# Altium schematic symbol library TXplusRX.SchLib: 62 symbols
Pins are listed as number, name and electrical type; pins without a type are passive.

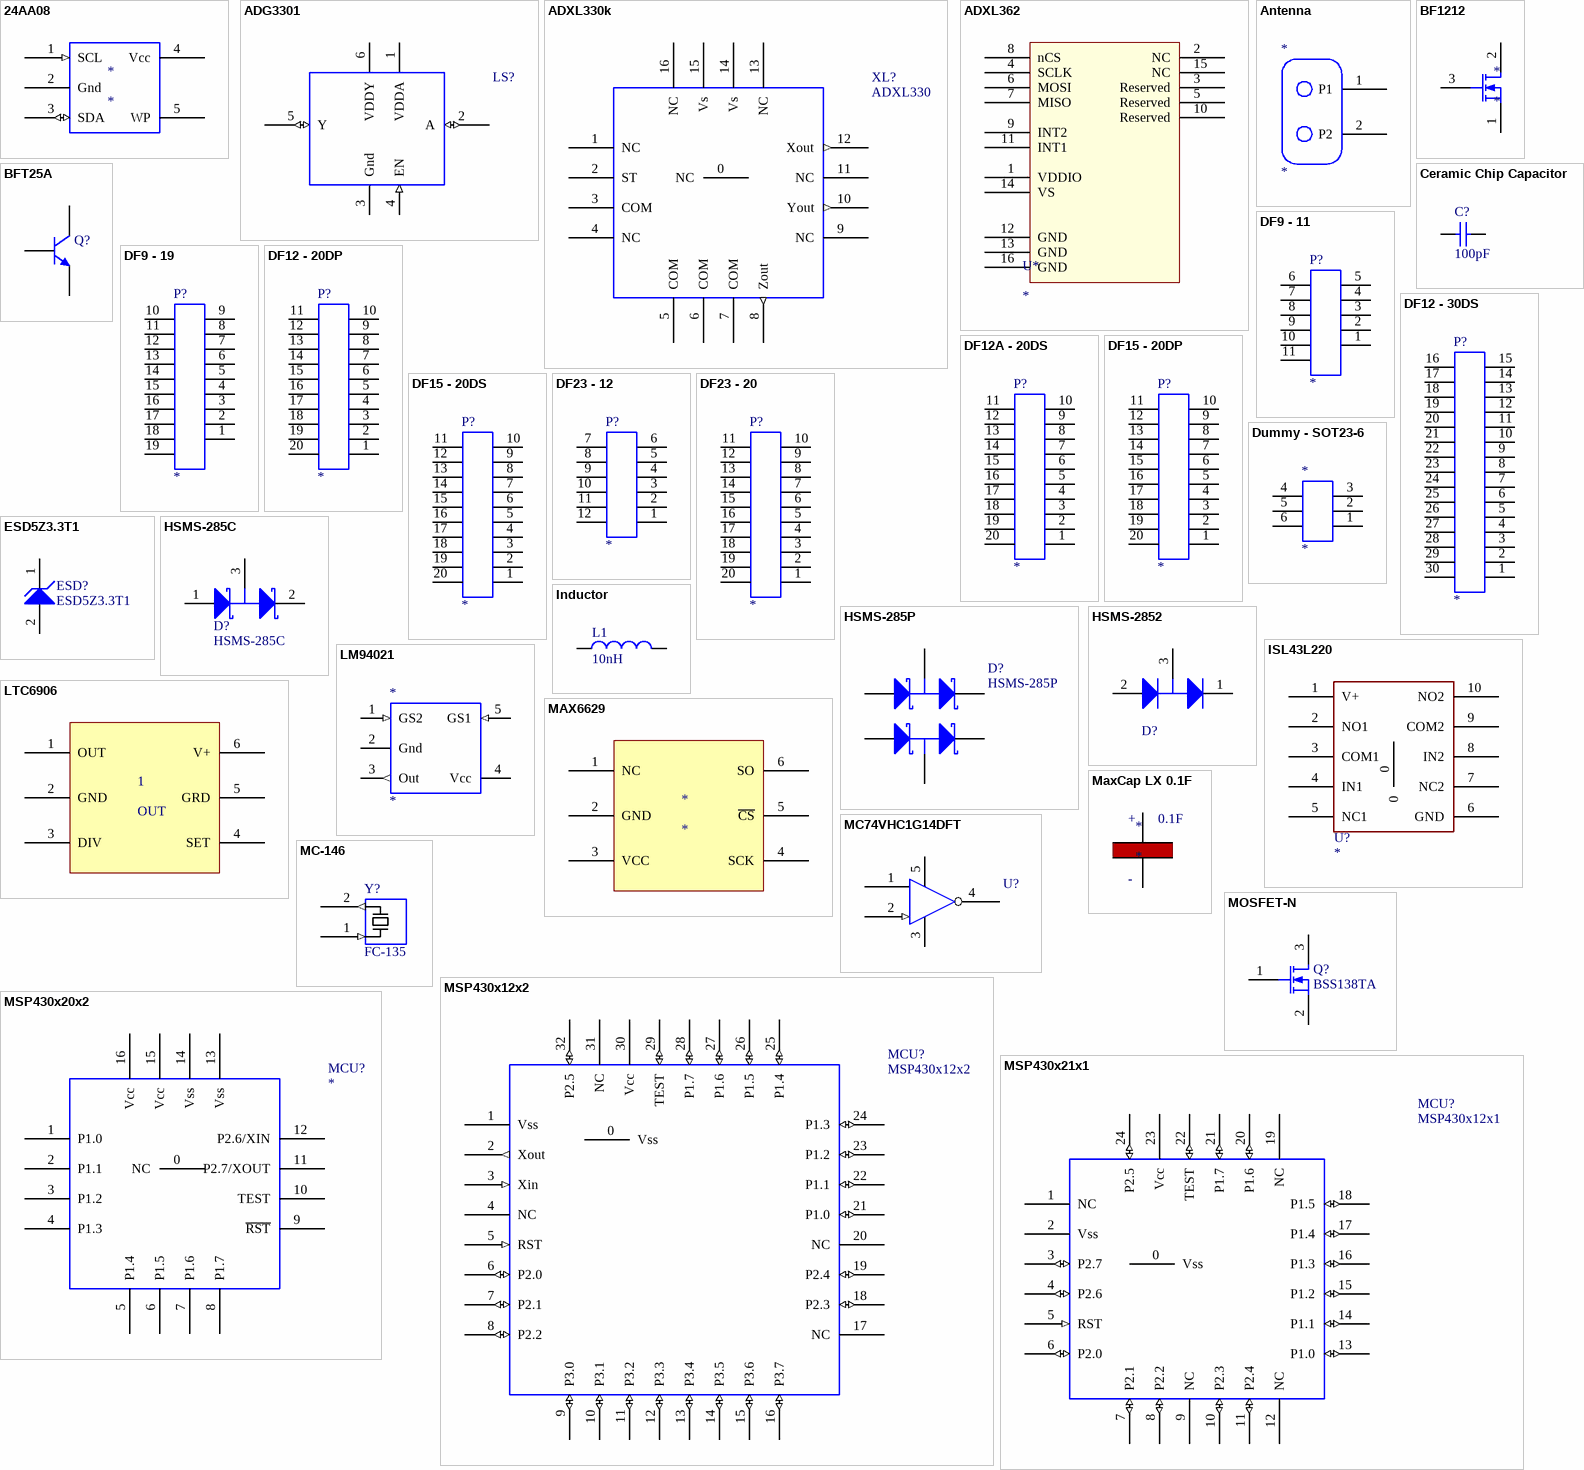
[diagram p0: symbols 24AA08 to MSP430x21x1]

## 24AA08
designator *
Microchip Technology - I2C SERIAL 8K EEPROM - 1.7v
footprint SOT-23-5 (SOT23, 5-Leads, Body 3.0x3.0mm (max), Pitch 0.95mm, IPC Medium Density)
pins: 1 SCL (in) "Serial Clock", 2 Gnd, 3 SDA (io) "Serial Address/Data I/O", 4 Vcc, 5 WP "Write_Protect Input"

## ADG3301
designator LS?  (value not drawn)
Level Shifter  Ensure:  VccA < VccY; DNS: Do Not Stuff Part
footprint sc70-6 (DIP; 24 Leads; Row Spacing 15.24 mm; Pitch 2.54 mm)
pins: 1 VDDA (power), 2 A (io) "Low Voltage IO", 3 Gnd (power), 4 EN (in) "Enable Output Translation", 5 Y (io) "High Voltage IO", 6 VDDY (power)

## ADXL330k
designator XL?, comment ADXL330
Analog Devices 3D Accelerometer
footprint 32-QFN - Gnd Pad Only (32-QFN, Gnd Pad Only, for MSP430F1232)
pins: 0 NC, 1 NC, 2 ST "Self Test", 3 COM (power) "GND", 4 NC, 5 COM (power) "GND", 6 COM (power) "GND", 7 COM (power) "GND", 8 Zout (out) "Output", 9 NC, 10 Yout (out), 11 NC, 12 Xout (out) "Output", 13 NC, 14 Vs (power) "2V to 3.6V", 15 Vs (power) "2V to 3.6V", 16 NC

## ADXL362
designator U*
Analog Devices low power accelerometer
footprint ADXL362
pins: 1 VDDIO, 2 NC, 3 Reserved, 4 SCLK, 5 Reserved, 6 MOSI, 7 MISO, 8 nCS, 9 INT2, 10 Reserved, 11 INT1, 12 GND, 13 GND, 14 VS, 15 NC, 16 GND

## Antenna
designator *
footprint antenna
pins: 1 P1 "Output", 2 P2 "Output"

## BF1212
designator *
footprint sot343r (SOT343R Package for BF1212)
pins: 1 S, 2 D, 3 G

## BFT25A
designator Q?
NPN 5 GHz Wideband Transistor; Part Number: BFT25A; DNS: Do Not Stuff Part
footprint SOT-23 (SOT-23; 3 Leads; Body 3.0 x 2.5 mm, inc. leads (LxW max))
pins: 1 B, 2 E, 3 C

## Ceramic Chip Capacitor
designator C?  value 100pF
Ceramic Capacitor - Standard; DNS: Do Not Stuff Part
footprint 0402 (Chip Capacitor; Body 1.0 x 0.5 mm (LxW typ))
footprint 0603 (Chip Capacitor; Body 1.6 x 0.8 mm (LxW typ))
footprint 0805 (Chip Capacitor; Body 2.0 x 1.2 mm (LxW typ))
footprint 1206 (Chip Capacitor; Body 3.2 x 1.6 mm (LxW typ))
footprint 1210 (Chip Capacitor; Body 3.2 x 2.5 mm (LxW typ))
footprint 1812 (Chip Capacitor; Body 4.5 x 3.2 mm (LxW typ))
footprint 1825 (Chip Capacitor; Body 4.5 x 6.4 mm (LxW typ))
pins: 1, 2

## DF9 - 11
designator P?
DF9 - 11 Connector; DNS: Do Not Stuff
footprint DF9 -11 Connector (DF9 -11, 11Pin Connector)
pins: 1, 2, 3, 4, 5, 6, 7, 8, 9, 10, 11

## DF9 - 19
designator P?
DF9 - 19 Connector; DNS: Do Not Stuff
footprint DF9 -19 Connector (DF9 -19, 19 Pin Connector)
pins: 1, 2, 3, 4, 5, 6, 7, 8, 9, 10, 11, 12, 13, 14, 15, 16, 17, 18, 19

## DF12 - 20DP
designator P?
DF12 - 20DP, Connector Header; DNS: Do Not Stuff
footprint DF12 - 20DP (DF12 - 20DP, Connector Header)
pins: 1, 2, 3, 4, 5, 6, 7, 8, 9, 10, 11, 12, 13, 14, 15, 16, 17, 18, 19, 20

## DF12 - 30DS
designator P?
DF12 - 30DS, Connector Receptacle; DNS: Do Not Stuff
footprint DF12 - 30DS (DF12 - 30DS, Connector Receptacle)
pins: 1, 2, 3, 4, 5, 6, 7, 8, 9, 10, 11, 12, 13, 14, 15, 16, 17, 18, 19, 20, 21, 22, 23, 24, 25, 26, 27, 28, 29, 30

## DF12A - 20DS
designator P?
DF12A - 20DS, Connector Receptacle; DNS: Do Not Stuff
footprint DF12 - 20DS (DF12 - 20DS, Connector Receptacle)
pins: 1, 2, 3, 4, 5, 6, 7, 8, 9, 10, 11, 12, 13, 14, 15, 16, 17, 18, 19, 20

## DF15 - 20DP
designator P?
DF15 - 20DP, Connector Header; DNS: Do Not Stuff
footprint DF15 - 20DP (DF15 - 20DP, Connector Header)
pins: 1, 2, 3, 4, 5, 6, 7, 8, 9, 10, 11, 12, 13, 14, 15, 16, 17, 18, 19, 20

## DF15 - 20DS
designator P?
DF15 - 20DS, Connector Receptacle; DNS: Do Not Stuff
footprint DF15 - 20DS (DF15 - 20DS, Connector Receptacle)
pins: 1, 2, 3, 4, 5, 6, 7, 8, 9, 10, 11, 12, 13, 14, 15, 16, 17, 18, 19, 20

## DF23 - 12
designator P?
DF23 - 12, Connector; DNS: Do Not Stuff
footprint DF23 - 12 (DF23 - 12, Connector)
pins: 1, 2, 3, 4, 5, 6, 7, 8, 9, 10, 11, 12

## DF23 - 20
designator P?
DF23 - 20 Connector; DNS: Do Not Stuff
footprint DF23 - 20 (DF23 - 20, Connector)
pins: 1, 2, 3, 4, 5, 6, 7, 8, 9, 10, 11, 12, 13, 14, 15, 16, 17, 18, 19, 20

## Dummy - SOT23-6
designator *
Dummy - SOT23-6
footprint SOT23-6 (SOT-457/SC-74; 6 Leads; Body 3 x 3 mm, inc. leads (LxW max))
pins: 1, 2, 3, 4, 5, 6

## ESD5Z3.3T1
designator ESD?
5V Overvoltage Protection Zener
footprint SOD-523 (SOD-523 Footprint)
pins: 1 C, 2 A

## HSMS-285C
designator D?
Agilent Schottky Diode, Bridge Quad, HSMS-285C
footprint SOT-323, HSMS-285C (SOT-323/SC-70; 3 Leads; HSMS-285C)
pins: 1 A, 2 K, 3 C

## HSMS-285P
designator D?
Agilent Schottky Diode, Bridge Quad, HSMS-285P
footprint SOT-363 (SOT-363 ,SC-88 ,6 Lead)
pins: 1 A, 2 C, 3 K, 4 K, 5 C, 6 A

## HSMS-2852
designator D?  (value not drawn)
Dual Schottky Diode RF
footprint SOT-23  WIDE
pins: 1, 2, 3

## Inductor
designator L1  value 10nH  (hidden comment: Inductor)
footprint 0805 (Chip Capacitor; Body 2.0 x 1.2 mm (LxW typ))
footprint 0603 (Chip Capacitor; Body 1.6 x 0.8 mm (LxW typ))
footprint 1206 (Chip Capacitor; Body 3.2 x 1.6 mm (LxW typ))
footprint 0402 (Chip Capacitor; Body 1.0 x 0.5 mm (LxW typ))
pins: 1, 2

## ISL43L220
designator U?
Ultra Low ON-Resistance, Low Voltage, Single Supply, Dual SPDT Analog Switch
footprint Thin Dual Flat No-Lead plastic Package (TDFN, 10-Leads, Body 3.0x3.0mm (max), Pitch 0.50mm, IPC Medium Density)
pins: 0, 1 V+, 2 NO1, 3 COM1, 4 IN1, 5 NC1, 6 GND, 7 NC2, 8 IN2, 9 COM2, 10 NO2

## LM94021
designator *
Temperature Sensor
footprint SC70 (Ultra low Power LDO - TI)
pins: 1 GS2 (in) "Gain Select 2", 2 Gnd (power), 3 Out (out) "Enable Output Translation", 4 Vcc (power) "Low Voltage IO", 5 GS1 (in) "Gain Select 1"

## LTC6906
designator 1, comment OUT
footprint LTC6906 (SOT23, 6-Leads, Body 2.90x2.80mm, Pitch 0.95mm, IPC Medium Density)
pins: 1 OUT, 2 GND, 3 DIV, 4 SET, 5 GRD, 6 V+

## MAX6629
designator *
footprint MAX6629-6632 (SOT23, 6-Leads, Body 2.90x2.80mm, Pitch 0.95mm, IPC Medium Density)
pins: 1 NC, 2 GND, 3 VCC, 4 SCK, 5 ~{CS}, 6 SO

## MaxCap LX 0.1F
designator *
MaxCap LX 0.1F, low leakage supper cap 5.5v
footprint Maxcap LX 0.1F (Maxcap LX Series, 0.1F, Diameter  11mm, Leads 5.1mm)
pins: 1 Positive (power), 2 GND (power)

## MC74VHC1G14DFT
designator U?  (value not drawn)
1uA CMOS Schmitt-Trigger Inverter
footprint SC70-5
pins: 1 NC, 2 A (in) "Input", 3 Gnd (power), 4 Y "Output", 5 VDD (power)

## MC-146
designator Y?, comment FC-135
FC-135 Crystal D-K SE2416CT (MC-146)
footprint FC-135 (FC-135   crystal - epson eletronics)
pins: 1 (in) "Output", 2 (out) "Output"

## MOSFET-N
designator Q?, comment BSS138TA
N-Channel MOSFET; PackageDocument: 1995/1996
footprint SOT-23 (SOT-23; 3 Leads; Body 3.0 x 2.5 mm, inc. leads (LxW max))
pins: 1 G, 2 S, 3 D

## MSP430x12x2
designator MCU?
32QFN MSP430x12x2
footprint 32-QFN (32-QFN, for MSP430F1232)
pins: 0 Vss (power) "Output", 1 Vss (power) "Output", 2 Xout (out) "Output", 3 Xin (in) "Output", 4 NC "Output", 5 RST (in) "Output", 6 P2.0 (io) "Output", 7 P2.1 (io) "Output", 8 P2.2 (io) "Output", 9 P3.0 (io) "Output", 10 P3.1 (io) "Output", 11 P3.2 (io) "Output", 12 P3.3 (io) "Output", 13 P3.4 (io) "Output", 14 P3.5 (io) "Output", 15 P3.6 (io) "Output", 16 P3.7 (io) "Output", 17 NC "Output", 18 P2.3 (io) "Output", 19 P2.4 (io) "Output", 20 NC "Output", 21 P1.0 (io) "Output", 22 P1.1 (io) "Output", 23 P1.2 (io) "Output", 24 P1.3 (io) "Output", 25 P1.4 (io) "Output", 26 P1.5 (io) "Output", 27 P1.6 (io) "Output", 28 P1.7 (io) "Output", 29 TEST (io) "Output", 30 Vcc (power) "Output", 31 NC "Output", 32 P2.5 (io) "Output"

## MSP430x20x2
designator MCU?
16QFN MSP430x20x2
footprint 16-QFN (16-QFN, LFCSP (CP-16-5) for ADXL330k)
pins: 0 NC, 1 P1.0, 2 P1.1 "Self Test", 3 P1.2 "GND", 4 P1.3, 5 P1.4 "GND", 6 P1.5 "GND", 7 P1.6 "GND", 8 P1.7 "Output", 9 ~{RST}, 10 TEST, 11 P2.7/XOUT, 12 P2.6/XIN "Output", 13 Vss (power), 14 Vss (power) "2V to 3.6V", 15 Vcc (power) "2V to 3.6V", 16 Vcc (power)

## MSP430x21x1
designator MCU?, comment MSP430x12x1
24QFN MSP430x21x1
footprint 24-QFN (24-QFN, for MSP430Fx21x1)
pins: 0 Vss (power) "Output", 1 NC "Output", 2 Vss (power) "Output", 3 P2.7 (io) "Output", 4 P2.6 (io) "Output", 5 RST (in) "Output", 6 P2.0 (io) "Output", 7 P2.1 (io) "Output", 8 P2.2 (io) "Output", 9 NC "Output", 10 P2.3 (io) "Output", 11 P2.4 (io) "Output", 12 NC "Output", 13 P1.0 (io) "Output", 14 P1.1 (io) "Output", 15 P1.2 (io) "Output", 16 P1.3 (io) "Output", 17 P1.4 (io) "Output", 18 P1.5 (io) "Output", 19 NC "Output", 20 P1.6 (io) "Output", 21 P1.7 (io) "Output", 22 TEST (io) "Output", 23 Vcc (power) "Output", 24 P2.5 (io) "Output"

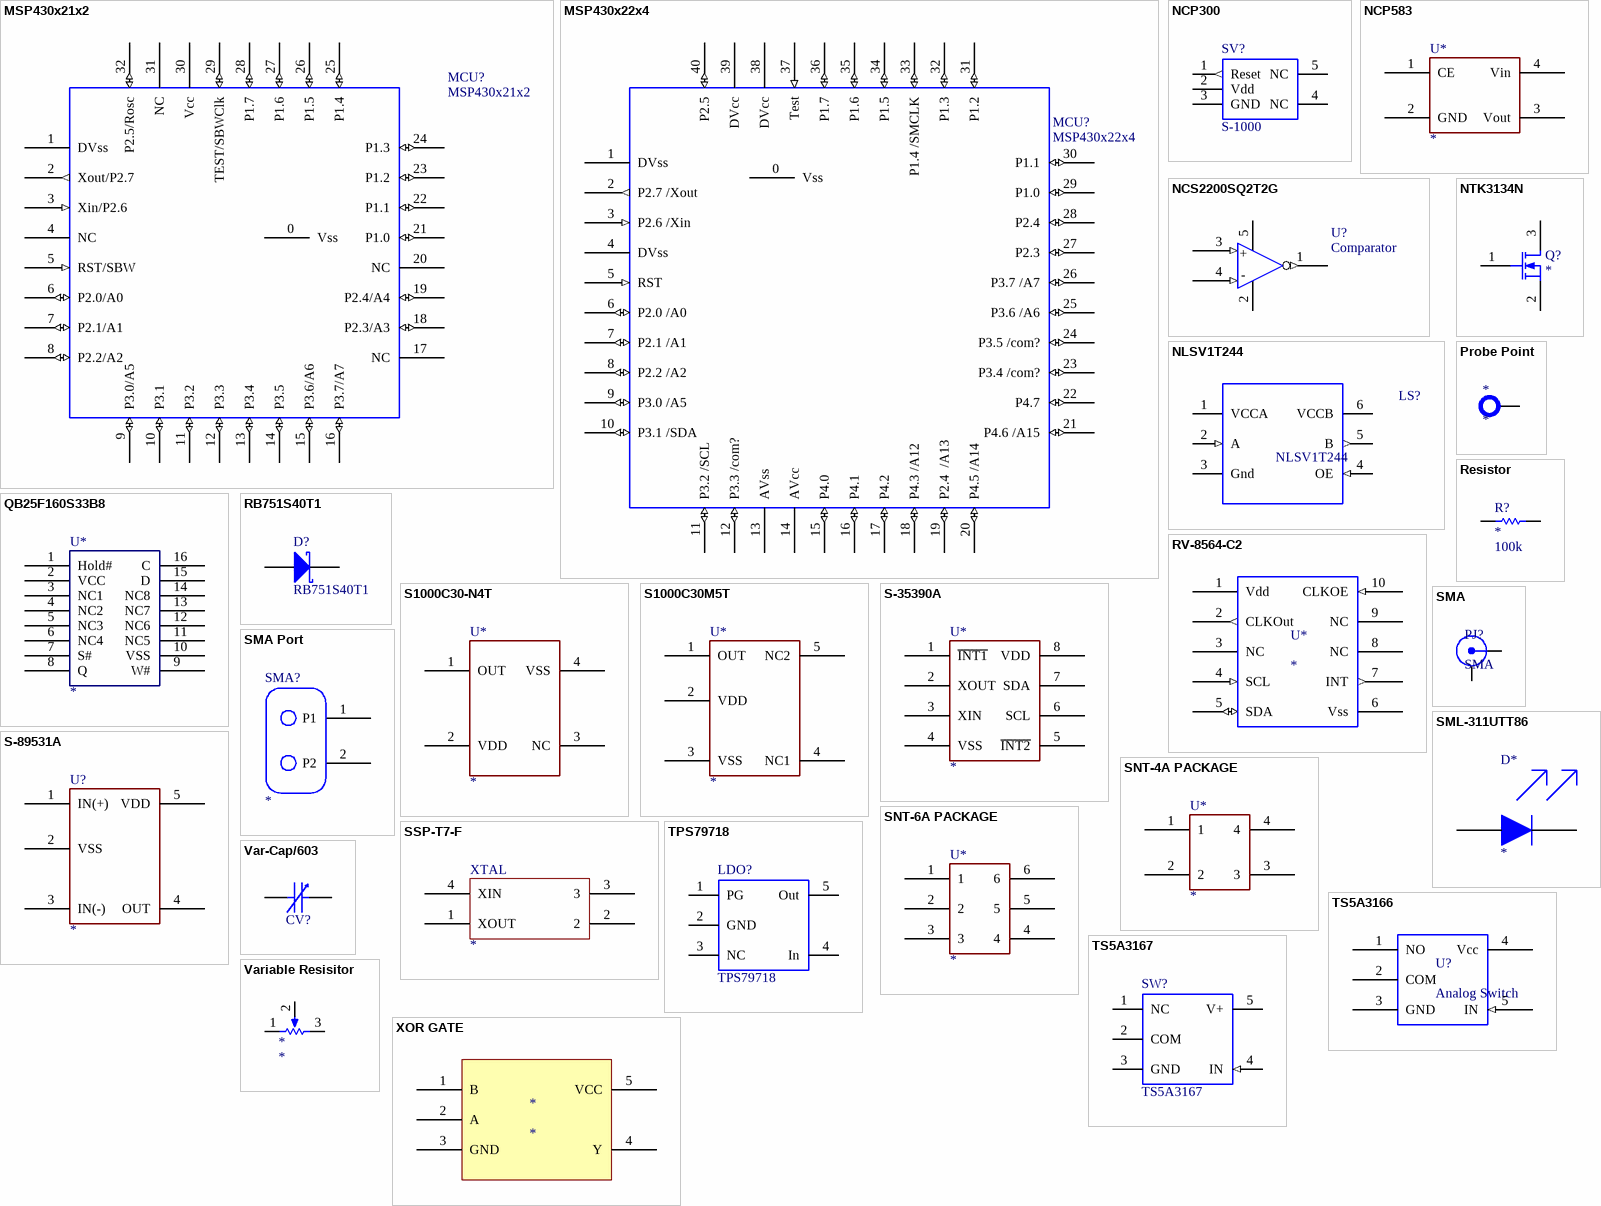
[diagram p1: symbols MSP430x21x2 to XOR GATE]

## MSP430x21x2
designator MCU?
32QFN MSP430x21x2
footprint 32-QFN (32-QFN, for MSP430F1232)
pins: 0 Vss (power) "Output", 1 DVss (power), 2 Xout/P2.7 (out), 3 Xin/P2.6 (in), 4 NC "Output", 5 RST/SBW (in), 6 P2.0/A0 (io), 7 P2.1/A1 (io) "Output", 8 P2.2/A2 (io) "Output", 9 P3.0/A5 (io), 10 P3.1 (io) "Output", 11 P3.2 (io) "Output", 12 P3.3 (io) "Output", 13 P3.4 (io) "Output", 14 P3.5 (io) "Output", 15 P3.6/A6 (io), 16 P3.7/A7 (io), 17 NC "Output", 18 P2.3/A3 (io) "Output", 19 P2.4/A4 (io) "Output", 20 NC "Output", 21 P1.0 (io) "Output", 22 P1.1 (io) "Output", 23 P1.2 (io) "Output", 24 P1.3 (io) "Output", 25 P1.4 (io) "Output", 26 P1.5 (io) "Output", 27 P1.6 (io) "Output", 28 P1.7 (io) "Output", 29 TEST/SBWClk (io) "Output", 30 Vcc (power) "Output", 31 NC "Output", 32 P2.5/Rosc (io) "Output"

## MSP430x22x4
designator MCU?
40QFN MSP430x22x4
footprint 40-QFN (QFN, 40-Leads, Body 6.2x6.2mm (max), Pitch 0.50mm, IPC Medium Density - MSP430x22x4)
pins: 0 Vss (power) "Output", 1 DVss (power) "Output", 2 P2.7 /Xout (out) "Output", 3 P2.6 /Xin (in) "Output", 4 DVss (power) "Output", 5 RST (in), 6 P2.0 /A0 (io), 7 P2.1 /A1 (io), 8 P2.2 /A2 (io), 9 P3.0 /A5 (io), 10 P3.1 /SDA (io), 11 P3.2 /SCL (io), 12 P3.3 /com? (io), 13 AVss (power), 14 AVcc (power), 15 P4.0 (io), 16 P4.1 (io), 17 P4.2 (io), 18 P4.3 /A12 (io), 19 P2.4  /A13 (io), 20 P4.5 /A14 (io), 21 P4.6 /A15 (io), 22 P4.7 (io), 23 P3.4 /com? (io), 24 P3.5 /com? (io), 25 P3.6 /A6 (io), 26 P3.7 /A7 (io), 27 P2.3 (io), 28 P2.4 (io), 29 P1.0 (io), 30 P1.1 (io), 31 P1.2 (io), 32 P1.3 (io), 33 P1.4 /SMCLK (io), 34 P1.5 (io), 35 P1.6 (io), 36 P1.7 (io), 37 Test (in), 38 DVcc (power), 39 DVcc (power), 40 P2.5 (io)

## NCP300
designator SV?, comment S-1000
300nA, 1.8V Supervisor (S-1000 or NCP300LSN)
footprint SOT-23-5 (SOT-23/SC-74A; 5 Leads; Body 3 x 3.1 mm, inc. leads (LxW max))
pins: 1 Reset (out), 2 Vdd (power), 3 GND (power), 4 NC, 5 NC

## NCP583
designator U*
Ultra-Low Iq 150mA CMOS LDO Regulator with Enable
footprint SC82-AB
pins: 1 CE, 2 GND, 3 Vout, 4 Vin

## NCS2200SQ2T2G
designator U?, comment Comparator
On Semi 10uA Comparator
footprint sc70-5 (SC70-5)
pins: 1 OUT (out) "Output", 2 Gnd (power), 3 IN+ (in) "Positive Input", 4 In- (in) "Inverting Input", 5 VDD (power)

## NLSV1T244
designator LS?
Level Shifter: 1-Bit Dual-Supply Non-Inverting Level Translator; Part Number: ADG3301; DNS: Do Not Stuff Part
footprint UDFN6 (UDFN6 - Level Shifter -  NLSV1T244)
pins: 1 VCCA (power) "VDDA", 2 A (in) "Low Voltage IO", 3 Gnd (power), 4 OE (in) "Enable Output Translation", 5 B (out) "High Voltage IO", 6 VCCB (power) "VDDY"

## NTK3134N
designator Q?
Powe Mosfet 20V, 890mA, Single N-channel
footprint SOT723 (SOT723, 3-Leads, Body 1.3x1.3mm (max), Pitch 0.40mm, IPC Medium Density)
pins: 1 G, 2 S, 3 D

## Probe Point
designator *
Probe Point for debug
footprint Probe Point (35mil Pad, 20mil hole size)
pins: 0

## QB25F160S33B8
designator U*
Intel Serial flash memory, 16Mbit, SOIC-16
footprint SOIC16 (SOIC 16)
pins: 1 Hold#, 2 VCC, 3 NC1, 4 NC2, 5 NC3, 6 NC4, 7 S#, 8 Q, 9 W#, 10 VSS, 11 NC5, 12 NC6, 13 NC7, 14 NC8, 15 D, 16 C

## RB751S40T1
designator D?
Schottky Diode
footprint SOD-523 (SOD-523 Footprint)
pins: 1 C, 2 A

## Resistor
designator R?  Vaule: 100k
Thick Film Resistor
footprint 0805 (Chip Capacitor; Body 2.0 x 1.2 mm (LxW typ))
footprint 0402 (Chip Capacitor; Body 1.0 x 0.5 mm (LxW typ))
footprint 0603 (Chip Capacitor; Body 1.6 x 0.8 mm (LxW typ))
pins: 1, 2

## RV-8564-C2
designator U*
RV-8564-C2, Real Time Clock
footprint RV-8564-C2 (RV-8564-C2 RTC Package: LCC, 10-Pins, Body 5.2x3.4mm (max), Pitch 1.00mm, IPC Medium Density)
pins: 1 Vdd (power), 2 CLKOut (out), 3 NC, 4 SCL (in), 5 SDA (io), 6 Vss (power), 7 INT (out), 8 NC, 9 NC, 10 CLKOE (in)

## S1000C30-N4T
designator U*
Ultra-small package High precision protection(SC82-AB)
footprint SC82-AB
pins: 1 OUT, 2 VDD, 3 NC, 4 VSS

## S1000C30M5T
designator U*
Ultra small package High precision voltage protection(SOT-23-5)
footprint SOT-23-5 (SOT-23/SC-74A; 5 Leads; Body 3 x 3.1 mm, inc. leads (LxW max))
pins: 1 OUT, 2 VDD, 3 VSS, 4 NC1, 5 NC2

## S-35390A
designator U*
2-WIRE-REAL-TIME CLOCK(SNT-8A)
footprint SNT-8A
pins: 1 ~{INT1}, 2 XOUT, 3 XIN, 4 VSS, 5 ~{INT2}, 6 SCL, 7 SDA, 8 VDD

## S-89531A
designator U?
0.7uA rail to rail cmos comparator
footprint SC-88A (SC-88A 5-Leads, Body 2.2x2.2mm (max), Pitch 0.65mm, IPC Medium Density)
pins: 1 IN(+), 2 VSS, 3 IN(-), 4 OUT, 5 VDD

## SMA
designator PJ?
footprint SMA
pins: 1 X, 2 Y

## SMA Port
designator SMA?
Two pin SMA connector wisp
footprint SMA Port (SMA port for wisp)
pins: 1 P1 "Output", 2 P2 "Output"

## SML-311UTT86
designator D*
LED 630NM RED WTR CLR 0603 SMD
footprint 0603 (Chip Capacitor; Body 1.6 x 0.8 mm (LxW typ))
pins: 1, 2

## SNT-4A PACKAGE
designator U*
SNT-4A PACKAGE
footprint SNT-4A
pins: 1, 2, 3, 4

## SNT-6A PACKAGE
designator U*
SNT-6A PACKAGE
footprint SNT-6A
pins: 1, 2, 3, 4, 5, 6

## SSP-T7-F
designator XTAL
Quartz Crystal-Surface Mount Type for Low Frequency
footprint XTAL 4 PIN
pins: 1 XOUT, 2, 3, 4 XIN

## TPS79718
designator LDO?
Ultra Low Power LDO - TI
footprint SOT-23-5 (SOT-23/SC-74A; 5 Leads; Body 3 x 3.1 mm, inc. leads (LxW max))
pins: 1 PG (oc), 2 GND (power), 3 NC, 4 In (power), 5 Out (power)

## TS5A3166
designator U?, comment Analog Switch
TI Analog Switch 100nA 1ohm Normally Open
footprint sc70-5 (SC70-5)
pins: 1 NO "Analog IO, Normally Open", 2 COM "Analog IO, Normally Open", 3 GND (power) "Ground", 4 Vcc (power) "1.65V to 6.5V", 5 IN (in) "Normally Open Switch Control"

## TS5A3167
designator SW?
TI 500nA, 1.65 to 5.5V Analog SPST Switch
footprint SC70 (Ultra low Power LDO - TI)
footprint SOT-23-5 (SOT-23/SC-74A; 5 Leads; Body 3 x 3.1 mm, inc. leads (LxW max))
pins: 1 NC "Normally Closed Connection", 2 COM "Common Port", 3 GND (power), 4 IN (in) "Control for Normally Closed Switch", 5 V+ (power) "1.65 to 5.5V"

## Var-Cap/603
designator CV?, comment Var Cap  (value not drawn)
Var-Cap 603 Compatible, DK: 490-2009 & SG2026CT; DNS: Do Not Stuff Part
footprint Var-Cap_603 (Var-Cap 603 Compatible, DK: 490-2009 & SG2026CT)
pins: 1 "Output", 2 "Output"

## Variable Resisitor
designator *
footprint Potentiometer-2mm(panasonic)
footprint Potentiometer-3mm(panasonic)
footprint potentiometer-4mm(panasonic)
pins: 1, 2, 3

## XOR GATE
designator *
footprint XOR GATE (SOT23, 5-Leads, Body 2.05x2.13mm, Pitch 0.65mm, IPC Medium Density)
pins: 1 B, 2 A, 3 GND, 4 Y, 5 VCC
